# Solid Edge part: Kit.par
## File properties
Author: bmolnar
Last saved by: bmolnar
Revision: 77
Sűrűség: 0,000 kg/m^3
Pontosság: 0,990
Username: bmolnar
Dokumentum tartalom típus: 0
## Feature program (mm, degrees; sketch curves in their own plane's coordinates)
base feature "unnamed BaseFeature 1"
thread "unnamed Thread 1"
thread "unnamed Thread 2"
thread "unnamed Thread 3"
thread "unnamed Thread 4"
sketch for "Furat_1" plane through (-38.5, 0, 123.75) normal (1, 0, 0) x-axis (0, 1, 0)
  hole centre (0, -32.25) bore radius 4.283
hole "Furat_1" nominal diameter 9.728 finite  ThreadDepth = 10 mm
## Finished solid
Body 1: solid body, 308 faces, 750 edges, 456 vertices.
  Faces by surface: plane 141, cylinder 75, swept 61, cone 20, torus 10, spline 1
  Edges by curve: line 431, circle 154, spline 126, ellipse 30, curve on surface 9
Bounding box of the edges (mm; curved faces can reach further): 77.000 x 77.000 x 13.750, from (-38.5, -38.5, 85.25) to (38.5, 38.5, 99).
Cylindrical faces by radius (mm): R0.2 x48, R0.2008 x2, R0.2009 x2, R0.402 x1, R0.4899 x1, R3.3235 x4, R4.283 x1, R4.9 x4, R5.15 x4, R5.25 x4, R8.27 x1, R8.85 x1, R9 x1, R10.25 x1
Conical faces (half-angle, radius in mm at the cone's reference point): 0.5 deg R12 x4, 0.5 deg R13.5 x2, 7 deg R9.5925 x1, 14 deg R8.135 x1, 14 deg R8.4811 x1, 17 deg R8.135 x1, 23 deg R8.829 x1, 42.5 deg R8.1233 x1, 45 deg R3.6735 x4, 45 deg R9 x1, 84 deg R8.4608 x1, 85 deg R9.9462 x1, 87 deg R8.1765 x1
Toroidal faces (ring radius, tube radius in mm): R4.7 r0.2 x8, R8.8057 r0.2025 x1, R9.2522 r0.2925 x1
Planar faces by outward normal: +x 12, +y 13, +z 19, -x 15, -y 14, -z 1, oblique 67
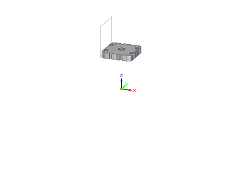
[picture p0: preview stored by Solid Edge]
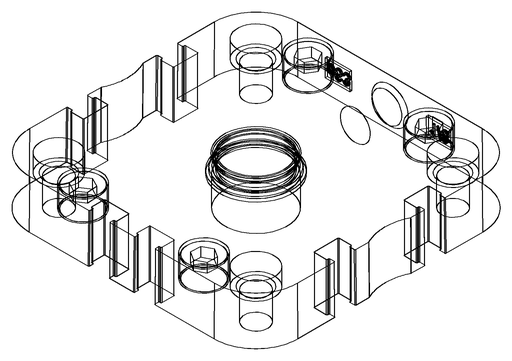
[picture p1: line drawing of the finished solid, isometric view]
